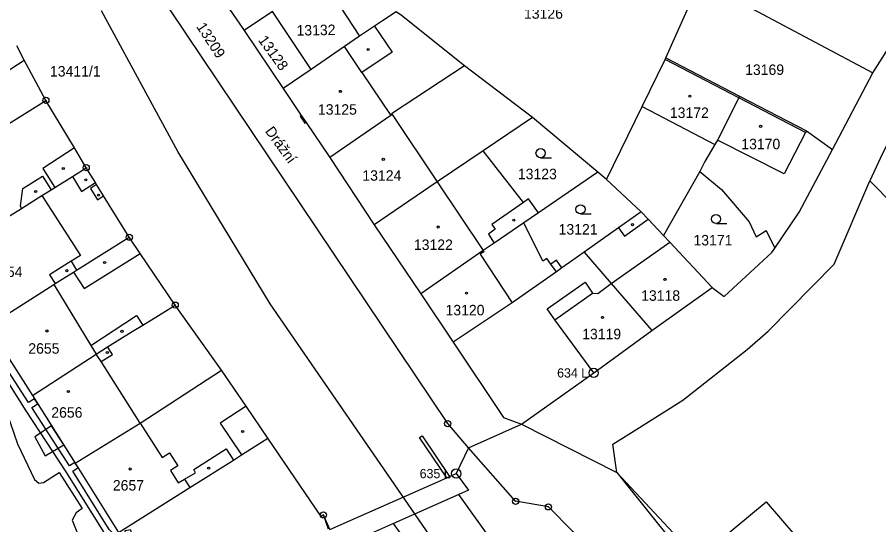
# Model space of a CAD drawing. Extents: x -821458 to -820266, y -1071458 to -1069826.
# Drawn here: x -820637.8 to -820498, y -1071294.1 to -1071211.7 of the extents above; entities that cross this region are included whole.
import ezdxf

# ---------------------------------------------------------------- set-up
doc = ezdxf.new("R2010")
doc.units = 0
for name, color, linetype in [('Vrstva 1', 7, 'Continuous'), ('Vrstva 13', 7, 'Continuous'), ('Vrstva 2', 7, 'Continuous'), ('Vrstva 3', 7, 'Continuous'), ('Vrstva 4', 7, 'Continuous'), ('Vrstva 5', 7, 'Continuous'), ('Vrstva 6', 7, 'Continuous'), ('Vrstva 7', 7, 'Continuous'), ('Vrstva 8', 7, 'Continuous')]:
    doc.layers.add(name, color=color, linetype=linetype)

msp = doc.modelspace()

# ---------------------------------------------------------------- linework, layer by layer
at = {"layer": 'Vrstva 1'}
for p, q in [((-820588.39, -1071205.33), (-820582.26, -1071214.75)), ((-820606.35, -1071205.94), (-820601.01, -1071213.82)), ((-820532.55, -1071218.25), (-820527.15, -1071206.13)), ((-820596.4, -1071210.72), (-820601.01, -1071213.82)), ((-820590.11, -1071220.12), (-820596.4, -1071210.72)), ((-820565.25, -1071219.52), (-820575.48, -1071211.38)), ((-820601.01, -1071213.82), (-820594.66, -1071223.23)), ((-820532.55, -1071218.25), (-820520.6, -1071224.45)), ((-820554.22, -1071227.91), (-820565.25, -1071219.52)), ((-820590.11, -1071220.12), (-820594.66, -1071223.23)), ((-820505.56, -1071233.12), (-820499.01, -1071220.67)), ((-820554.22, -1071227.91), (-820562.23, -1071233.35)), ((-820543.61, -1071236.82), (-820554.22, -1071227.91)), ((-820587.11, -1071234.42), (-820579.87, -1071245.35)), ((-820543.61, -1071236.82), (-820553.23, -1071243.42)), ((-820542.2, -1071238.02), (-820543.61, -1071236.82)), ((-820527.07, -1071236.71), (-820532.94, -1071247.11)), ((-820536.58, -1071243.26), (-820542.2, -1071238.02)), ((-820553.23, -1071243.42), (-820555.62, -1071245.05)), ((-820579.87, -1071245.35), (-820572.35, -1071256.57)), ((-820534.83, -1071262.53), (-820525.08, -1071255.54)), ((-820572.35, -1071256.57), (-820567.06, -1071264.43)), ((-820604.65, -1071268.97), (-820612.18, -1071258.39)), ((-820642.52, -1071261.82), (-820635.34, -1071273.05)), ((-820635.34, -1071273.05), (-820628.38, -1071284.03)), ((-820564.58, -1071281.57), (-820555.99, -1071277.72)), ((-820555.99, -1071277.72), (-820540.54, -1071285.54)), ((-820628.38, -1071284.03), (-820621.4, -1071295.3))]:
    msp.add_line(p, q, dxfattribs=at)
for points in [[(-820564.58, -1071281.57), (-820567.96, -1071277.63), (-820613.1, -1071210.27), (-820636.96, -1071169.72)], [(-820499.01, -1071220.67), (-820495.3, -1071214.89), (-820490.07, -1071207.98)], [(-820520.63, -1071209.32), (-820517.72, -1071210.75), (-820499.01, -1071220.67)], [(-820575.48, -1071211.38), (-820576.31, -1071210.76), (-820578.57, -1071212.22), (-820579.84, -1071213.09), (-820582.26, -1071214.75)], [(-820582.26, -1071214.75), (-820584.7, -1071216.43), (-820590.11, -1071220.12)], [(-820633.16, -1071225.15), (-820636.66, -1071218.6), (-820637.88, -1071216.32)], [(-820542.2, -1071238.02), (-820536.44, -1071226.16), (-820532.67, -1071218.53), (-820532.55, -1071218.25)], [(-820565.25, -1071219.52), (-820577.08, -1071227.33), (-820576.97, -1071227.46), (-820577.21, -1071227.63), (-820587.11, -1071234.42)], [(-820489.97, -1071219.33), (-820490.59, -1071220.12), (-820497.82, -1071234.6), (-820499.47, -1071238.21)], [(-820594.66, -1071223.23), (-820591.73, -1071227.59), (-820590.95, -1071228.74), (-820587.11, -1071234.42)], [(-820656.41, -1071239.65), (-820645.74, -1071233.01), (-820633.16, -1071225.15)], [(-820626.61, -1071236.09), (-820628.53, -1071232.88), (-820633.16, -1071225.15)], [(-820520.6, -1071224.45), (-820520.73, -1071224.72), (-820524.17, -1071231.61), (-820524.6, -1071232.33), (-820526.26, -1071235.07), (-820527.07, -1071236.71)], [(-820520.6, -1071224.45), (-820509.76, -1071230.08), (-820505.56, -1071233.12)], [(-820562.23, -1071233.35), (-820569.68, -1071238.4), (-820579.87, -1071245.35)], [(-820553.23, -1071243.42), (-820554.83, -1071241.14), (-820555.68, -1071241.74), (-820562.23, -1071233.35)], [(-820514.89, -1071249.14), (-820510.92, -1071243.31), (-820505.56, -1071233.12)], [(-820499.47, -1071238.21), (-820484.08, -1071253.85), (-820465.21, -1071237.36), (-820468.35, -1071234.19)], [(-820649.59, -1071250.53), (-820638.94, -1071243.84), (-820637.11, -1071242.69), (-820633.8, -1071240.61), (-820632.28, -1071239.66), (-820631.69, -1071239.28), (-820628.85, -1071237.5), (-820626.61, -1071236.09)], [(-820619.63, -1071247.37), (-820623.79, -1071240.65), (-820624.92, -1071238.81), (-820625.11, -1071238.51), (-820626.61, -1071236.09)], [(-820527.07, -1071236.71), (-820523.54, -1071239.61), (-820519.08, -1071244.89), (-820517.94, -1071247.3), (-820516.27, -1071246.29), (-820514.89, -1071249.14)], [(-820540.54, -1071285.54), (-820541.2, -1071280.96), (-820537.27, -1071278.55), (-820529.82, -1071273.81), (-820519.39, -1071265.59), (-820515.99, -1071262.62), (-820505.24, -1071251.73), (-820499.47, -1071238.21)], [(-820536.58, -1071243.26), (-820540.25, -1071245.86), (-820545.8, -1071249.8)], [(-820532.94, -1071247.11), (-820535.45, -1071244.46), (-820536.58, -1071243.26)], [(-820555.62, -1071245.05), (-820560.4, -1071248.31), (-820562.23, -1071249.55), (-820572.35, -1071256.57)], [(-820549.44, -1071252.34), (-820550.32, -1071251.09), (-820551.22, -1071251.72), (-820551.87, -1071250.81), (-820552.52, -1071251.26), (-820555.62, -1071245.05)], [(-820642.52, -1071261.82), (-820631.89, -1071255.05), (-820631.65, -1071254.9), (-820628.68, -1071253.04), (-820628.17, -1071252.72), (-820619.63, -1071247.37)], [(-820612.18, -1071258.39), (-820617.84, -1071250.03), (-820619.63, -1071247.37)], [(-820525.08, -1071255.54), (-820531.95, -1071248.19), (-820532.94, -1071247.11)], [(-820545.8, -1071249.8), (-820547.69, -1071251.1), (-820549.44, -1071252.34)], [(-820545.8, -1071249.8), (-820541.44, -1071254.9), (-820534.83, -1071262.53)], [(-820525.08, -1071255.54), (-820523.12, -1071256.99), (-820515.37, -1071249.84), (-820514.89, -1071249.14)], [(-820549.44, -1071252.34), (-820550.34, -1071252.97), (-820557.48, -1071258), (-820567.06, -1071264.43)], [(-820635.34, -1071273.05), (-820624.98, -1071266.36), (-820623.18, -1071265.19), (-820619.15, -1071262.7), (-820617.43, -1071261.64), (-820614.9, -1071260.07), (-820612.18, -1071258.39)], [(-820555.99, -1071277.72), (-820544.28, -1071269.4), (-820534.83, -1071262.53)], [(-820567.06, -1071264.43), (-820558.89, -1071276.65), (-820555.99, -1071277.72)], [(-820628.38, -1071284.03), (-820617.86, -1071277.55), (-820604.65, -1071268.97)], [(-820597.17, -1071279.98), (-820600.69, -1071274.81), (-820604.65, -1071268.97)], [(-820621.4, -1071295.3), (-820609.81, -1071287.99), (-820602.74, -1071283.57), (-820601.4, -1071282.71), (-820597.17, -1071279.98)], [(-820587.31, -1071294.74), (-820588.13, -1071292.45), (-820588.5, -1071292.71), (-820597.17, -1071279.98)], [(-820485.86, -1071372.38), (-820533.17, -1071312.78), (-820547.67, -1071295.15), (-820551.62, -1071291.15), (-820556.95, -1071290.24), (-820564.58, -1071281.57)], [(-820510.8, -1071317.69), (-820522.19, -1071305.22), (-820540.54, -1071285.54)], [(-820510.8, -1071317.69), (-820526.79, -1071299.05), (-820516.32, -1071290.31), (-820500.02, -1071309.25)]]:
    msp.add_lwpolyline(points, dxfattribs=at)
at = {"layer": 'Vrstva 13'}
msp.add_lwpolyline([(-820650.46, -1071253.28), (-820636.39, -1071275.54), (-820629.91, -1071285.45), (-820623.66, -1071295.46), (-820622.08, -1071296.95), (-820620.34, -1071296.92), (-820619.15, -1071296.11), (-820619.37, -1071294.88), (-820620.35, -1071295.06), (-820620.25, -1071295.65), (-820620.61, -1071295.9), (-820621, -1071295.91), (-820621.7, -1071295.93), (-820622.88, -1071294.82), (-820628.8, -1071285.34), (-820627.91, -1071284.78), (-820628.38, -1071284.03), (-820628.44, -1071283.93), (-820629.34, -1071284.49), (-820635.43, -1071275.04), (-820634.47, -1071274.43), (-820635, -1071273.59), (-820635.97, -1071274.2), (-820643.14, -1071263.21)], dxfattribs=at)
msp.add_lwpolyline([(-820632.22, -1071277.97), (-820634.97, -1071279.75), (-820633.3, -1071282.84), (-820630.27, -1071281.05)], close=True, dxfattribs=at)
at = {"layer": 'Vrstva 3'}
for p, q in [((-820552.89, -1071234.48), (-820551.14, -1071234.48)), ((-820546.42, -1071243.59), (-820544.67, -1071243.59)), ((-820524.43, -1071245.17), (-820522.68, -1071245.17))]:
    msp.add_line(p, q, dxfattribs=at)
for centre in [(-820552.89, -1071233.73), (-820546.42, -1071242.84), (-820524.43, -1071244.42)]:
    msp.add_circle(centre, 0.75, dxfattribs=at)
at = {"layer": 'Vrstva 4'}
for p, q in [((-820579.84, -1071213.09), (-820576.97, -1071217.31)), ((-820581.88, -1071220.64), (-820584.7, -1071216.43)), ((-820576.97, -1071217.31), (-820581.88, -1071220.64)), ((-820645.82, -1071224.5), (-820636.66, -1071218.6)), ((-820520.73, -1071224.72), (-820532.67, -1071218.53)), ((-820581.88, -1071220.64), (-820577.21, -1071227.63)), ((-820509.9, -1071230.35), (-820520.73, -1071224.72)), ((-820536.44, -1071226.16), (-820524.6, -1071232.33)), ((-820591.73, -1071227.59), (-820591.92, -1071227.71)), ((-820591.92, -1071227.71), (-820591.14, -1071228.87)), ((-820576.97, -1071227.46), (-820569.68, -1071238.4)), ((-820591.14, -1071228.87), (-820590.95, -1071228.74)), ((-820509.9, -1071230.35), (-820513.4, -1071237.1)), ((-820509.76, -1071230.08), (-820509.9, -1071230.35)), ((-820513.4, -1071237.1), (-820524.17, -1071231.61)), ((-820628.53, -1071232.88), (-820633.67, -1071236.2)), ((-820633.67, -1071236.2), (-820631.69, -1071239.28)), ((-820636.88, -1071239.48), (-820633.69, -1071237.44)), ((-820633.69, -1071237.44), (-820632.28, -1071239.66)), ((-820628.85, -1071237.5), (-820627.37, -1071239.95)), ((-820627.37, -1071239.95), (-820625.11, -1071238.51)), ((-820624.92, -1071238.81), (-820625.94, -1071239.44)), ((-820569.68, -1071238.4), (-820562.23, -1071249.55)), ((-820637.27, -1071242.25), (-820636.88, -1071239.48)), ((-820633.8, -1071240.61), (-820627.56, -1071250.34)), ((-820625.94, -1071239.44), (-820624.81, -1071241.28)), ((-820624.81, -1071241.28), (-820623.79, -1071240.65)), ((-820555.68, -1071241.74), (-820560.8, -1071245.32)), ((-820637.11, -1071242.69), (-820637.27, -1071242.25)), ((-820539.27, -1071247.22), (-820535.45, -1071244.46)), ((-820560.28, -1071246.06), (-820561.32, -1071246.87)), ((-820560.8, -1071245.32), (-820560.28, -1071246.06)), ((-820540.25, -1071245.86), (-820539.27, -1071247.22)), ((-820561.32, -1071246.87), (-820560.4, -1071248.31)), ((-820541.44, -1071254.9), (-820531.95, -1071248.19)), ((-820627.56, -1071250.34), (-820629.08, -1071251.28)), ((-820626.95, -1071255.67), (-820617.84, -1071250.03)), ((-820562.1, -1071249.74), (-820562.68, -1071250.14)), ((-820562.68, -1071250.14), (-820557.48, -1071258)), ((-820562.23, -1071249.55), (-820562.1, -1071249.74)), ((-820629.08, -1071251.28), (-820632.56, -1071253.45)), ((-820629.08, -1071251.28), (-820628.17, -1071252.72)), ((-820550.34, -1071252.97), (-820551.22, -1071251.72)), ((-820628.68, -1071253.04), (-820626.95, -1071255.67)), ((-820632.56, -1071253.45), (-820631.65, -1071254.9)), ((-820631.89, -1071255.05), (-820625.85, -1071264.94)), ((-820551.83, -1071259.02), (-820545.68, -1071254.67)), ((-820545.68, -1071254.67), (-820544.47, -1071256.44)), ((-820543.62, -1071256.51), (-820541.44, -1071254.9)), ((-820550.56, -1071260.76), (-820544.47, -1071256.44)), ((-820544.47, -1071256.44), (-820543.62, -1071256.51)), ((-820625.85, -1071264.94), (-820618.44, -1071260.1)), ((-820618.44, -1071260.1), (-820617.43, -1071261.64)), ((-820550.56, -1071260.76), (-820551.83, -1071259.02)), ((-820544.28, -1071269.4), (-820550.56, -1071260.76)), ((-820625.85, -1071264.94), (-820624.98, -1071266.36)), ((-820622.34, -1071266.39), (-820623.18, -1071265.19)), ((-820624.21, -1071267.57), (-820624.98, -1071266.36)), ((-820624.21, -1071267.57), (-820622.34, -1071266.39)), ((-820617.86, -1071277.55), (-820624.21, -1071267.57)), ((-820640.15, -1071273.97), (-820637.77, -1071280.9)), ((-820600.69, -1071274.81), (-820604.89, -1071277.55)), ((-820617.86, -1071277.55), (-820614.31, -1071283.15)), ((-820604.89, -1071277.55), (-820601.4, -1071282.71)), ((-820572.54, -1071279.89), (-820572.13, -1071279.61)), ((-820572.13, -1071279.61), (-820567.68, -1071286.23)), ((-820637.77, -1071280.9), (-820634.98, -1071286.72)), ((-820568.13, -1071286.43), (-820572.54, -1071279.89)), ((-820614.31, -1071283.15), (-820613.12, -1071282.39)), ((-820613.12, -1071282.39), (-820611.77, -1071284.51)), ((-820609.17, -1071285.1), (-820603.91, -1071281.72)), ((-820603.91, -1071281.72), (-820602.74, -1071283.57)), ((-820564.58, -1071281.57), (-820566.58, -1071285.74)), ((-820611.77, -1071284.51), (-820612.95, -1071285.26)), ((-820612.95, -1071285.26), (-820611.68, -1071287.27)), ((-820608.88, -1071285.6), (-820609.17, -1071285.1)), ((-820634.98, -1071286.72), (-820634.31, -1071287.28)), ((-820633.57, -1071287.19), (-820631.01, -1071285.59)), ((-820631.01, -1071285.59), (-820627.29, -1071291.43)), ((-820611.68, -1071287.27), (-820610.67, -1071286.63)), ((-820610.67, -1071286.63), (-820608.88, -1071285.6)), ((-820610.67, -1071286.63), (-820609.81, -1071287.99)), ((-820578.74, -1071291.13), (-820568.13, -1071286.43)), ((-820568.13, -1071286.43), (-820567.68, -1071286.23)), ((-820567.68, -1071286.23), (-820566.58, -1071285.74)), ((-820566.58, -1071285.74), (-820564.61, -1071288.46)), ((-820540.54, -1071285.54), (-820479.66, -1071361.53)), ((-820634.31, -1071287.28), (-820633.57, -1071287.19)), ((-820566.17, -1071289.15), (-820576.77, -1071293.84)), ((-820564.61, -1071288.46), (-820566.17, -1071289.15)), ((-820558.94, -1071299.19), (-820566.17, -1071289.15)), ((-820628.27, -1071292.1), (-820628.9, -1071293.32)), ((-820627.29, -1071291.43), (-820628.27, -1071292.1)), ((-820587.08, -1071294.82), (-820578.74, -1071291.13)), ((-820628.9, -1071293.32), (-820628.16, -1071295.22)), ((-820587.08, -1071294.82), (-820588.13, -1071292.45)), ((-820576.77, -1071293.84), (-820585.13, -1071297.55)), ((-820569.54, -1071303.79), (-820576.77, -1071293.84))]:
    msp.add_line(p, q, dxfattribs=at)
at = {"layer": 'Vrstva 5'}
for centre in [(-820580.88, -1071216.89), (-820585.37, -1071223.7), (-820528.69, -1071224.48), (-820517.2, -1071229.37), (-820578.41, -1071234.73), (-820630.34, -1071236.21), (-820626.68, -1071238.05), (-820634.82, -1071239.95), (-820624.62, -1071240.54), (-820557.23, -1071244.6), (-820569.51, -1071245.72), (-820537.99, -1071245.33), (-820623.63, -1071251.47), (-820629.77, -1071252.8), (-820532.71, -1071254.22), (-820564.92, -1071256.46), (-820542.84, -1071260.39), (-820632.99, -1071262.58), (-820620.82, -1071262.65), (-820623.18, -1071266.08), (-820629.5, -1071272.41), (-820601.24, -1071278.91), (-820619.49, -1071284.99), (-820606.76, -1071284.87)]:
    msp.add_circle(centre, 0.175, dxfattribs=at)
at = {"layer": 'Vrstva 6'}
for p, q in [((-820611.74, -1071233.47), (-820624.12, -1071210.63)), ((-820596.75, -1071258.19), (-820611.74, -1071233.47)), ((-820561.35, -1071309.57), (-820596.75, -1071258.19))]:
    msp.add_line(p, q, dxfattribs=at)
at = {"layer": 'Vrstva 8'}
for centre, radius in [((-820633.16, -1071225.15), 0.5), ((-820633.16, -1071225.15), 0.0303), ((-820626.61, -1071236.09), 0.5), ((-820626.61, -1071236.09), 0.0303), ((-820619.63, -1071247.37), 0.5), ((-820619.63, -1071247.37), 0.0303), ((-820612.18, -1071258.39), 0.5), ((-820612.18, -1071258.39), 0.0303), ((-820544.28, -1071269.4), 0.75), ((-820544.28, -1071269.4), 0.03), ((-820567.96, -1071277.63), 0.5), ((-820567.96, -1071277.63), 0.0303), ((-820566.58, -1071285.74), 0.75), ((-820566.58, -1071285.74), 0.03), ((-820556.95, -1071290.24), 0.5), ((-820556.95, -1071290.24), 0.0303), ((-820551.62, -1071291.15), 0.5), ((-820588.13, -1071292.45), 0.5), ((-820551.62, -1071291.15), 0.0303), ((-820588.13, -1071292.45), 0.0303)]:
    msp.add_circle(centre, radius, dxfattribs=at)

# ---------------------------------------------------------------- texts
at = {"layer": 'Vrstva 2'}
for s, p in [('13126', (-820555.59, -1071211.9)), ('13411/1', (-820632.5, -1071221.28)), ('13169', (-820519.71, -1071221.02)), ('13125', (-820589.02, -1071227.48)), ('13172', (-820531.92, -1071228.01)), ('13170', (-820520.33, -1071233.09)), ('13124', (-820581.81, -1071238.2)), ('13123', (-820556.58, -1071237.95)), ('13121', (-820549.97, -1071246.94)), ('13171', (-820528.09, -1071248.7)), ('13122', (-820573.45, -1071249.44)), ('2654', (-820642.01, -1071253.83)), ('13118', (-820536.58, -1071257.69)), ('13120', (-820568.32, -1071260.05)), ('13119', (-820546.15, -1071263.94)), ('2655', (-820636.01, -1071266.28)), ('2656', (-820632.28, -1071276.67)), ('2657', (-820622.29, -1071288.5))]:
    msp.add_text(s, height=1.7, dxfattribs=at).set_placement(p)
for s, rotation, p in [('13209', 303, (-820608.81, -1071213.19)), ('13132', 1, (-820592.48, -1071214.65)), ('13128', 306, (-820598.8, -1071215.38))]:
    msp.add_text(s, height=1.7, rotation=rotation, dxfattribs=at).set_placement(p)
at = {"layer": 'Vrstva 7'}
msp.add_text('Drážní', height=1.7, rotation=306, dxfattribs=at).set_placement((-820597.67, -1071230.16))
at = {"layer": 'Vrstva 8'}
for s, p in [('634 L', (-820550.21, -1071270.15)), ('635 L', (-820572.51, -1071286.49))]:
    msp.add_text(s, height=1.5, dxfattribs=at).set_placement(p)

doc.saveas('drawing.dxf')
